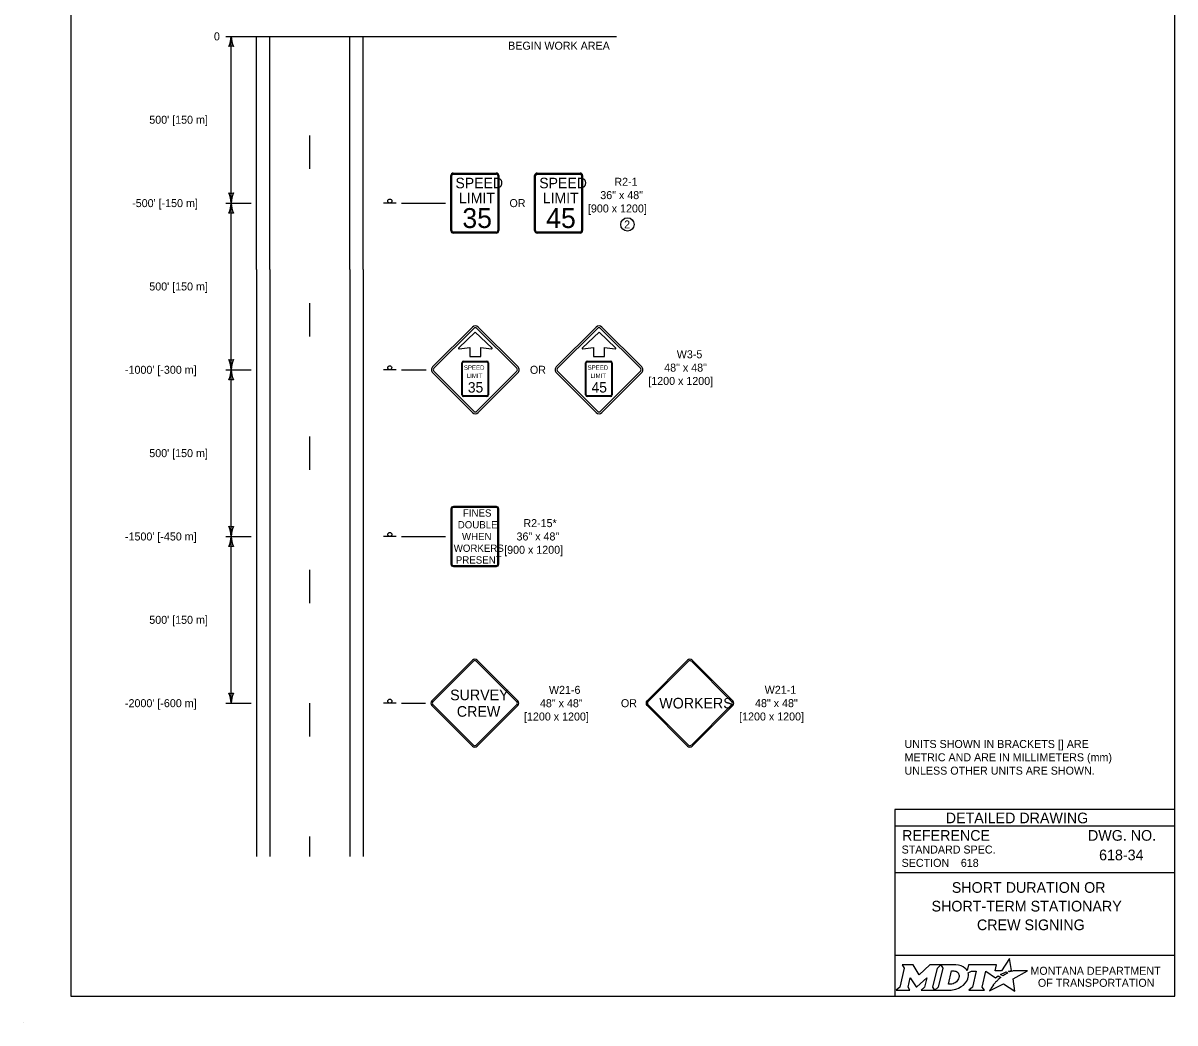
# Model space of a CAD drawing. Extents: x 49991.4 to 50021, y 49987.6 to 50011.4.
# Drawn here: x 49999.98 to 50008.61, y 49999.86 to 50007.36 of the extents above; entities that cross this region are included whole.
import ezdxf

# ---------------------------------------------------------------- set-up
doc = ezdxf.new("R2010")
doc.units = 0
for name, color, linetype in [('Level 1', 7, 'Continuous'), ('Level 2', 7, 'Continuous'), ('Level 3', 7, 'Continuous')]:
    doc.layers.add(name, color=color, linetype=linetype)

msp = doc.modelspace()

# ---------------------------------------------------------------- linework, layer by layer
at = {"layer": 'Level 1'}
for p, q in [((50001.7269, 50005.5137), (50001.7269, 50007.2611)), ((50001.8269, 50005.5137), (50001.8269, 50007.2611)), ((50002.4269, 50005.5137), (50002.4269, 50007.2611)), ((50002.5269, 50005.5137), (50002.5269, 50007.2611)), ((50002.1269, 50006.2688), (50002.1269, 50006.5188)), ((50003.1843, 50005.8044), (50003.1843, 50006.217)), ((50003.1918, 50005.8044), (50003.1918, 50006.217)), ((50003.203, 50006.2357), (50003.5256, 50006.2357)), ((50003.203, 50006.2282), (50003.5256, 50006.2282)), ((50003.5368, 50006.217), (50003.5368, 50005.8044)), ((50003.5443, 50006.217), (50003.5443, 50005.8044)), ((50003.8127, 50005.8045), (50003.8127, 50006.2169)), ((50003.8202, 50005.8045), (50003.8202, 50006.2169)), ((50003.8314, 50006.2357), (50004.154, 50006.2357)), ((50003.8314, 50006.2282), (50004.154, 50006.2282)), ((50004.1652, 50006.2169), (50004.1652, 50005.8045)), ((50004.1727, 50006.2169), (50004.1727, 50005.8045)), ((50002.7749, 50006.0107), (50002.6789, 50006.0107)), ((50003.5256, 50005.7932), (50003.203, 50005.7932)), ((50003.5256, 50005.7857), (50003.203, 50005.7857)), ((50004.154, 50005.7932), (50003.8314, 50005.7932)), ((50004.154, 50005.7857), (50003.8314, 50005.7857)), ((50001.7269, 50005.5137), (50001.7269, 50001.1107)), ((50001.8269, 50005.5137), (50001.8269, 50001.1107)), ((50002.4269, 50005.5137), (50002.4269, 50001.1107)), ((50002.5269, 50005.5137), (50002.5269, 50001.1107)), ((50002.1269, 50005.0111), (50002.1269, 50005.2611)), ((50003.3468, 50005.0813), (50003.0475, 50004.782)), ((50003.3569, 50005.0712), (50003.0576, 50004.7719)), ((50003.3682, 50005.0428), (50003.2438, 50004.9255)), ((50003.3468, 50005.0813), (50003.3468, 50005.0813)), ((50003.3569, 50005.0712), (50003.3569, 50005.0712)), ((50003.4926, 50004.9255), (50003.3682, 50005.0428)), ((50003.6788, 50004.7719), (50003.3795, 50005.0712)), ((50003.6889, 50004.782), (50003.3896, 50005.0813)), ((50004.2743, 50005.0813), (50003.9749, 50004.782)), ((50004.2843, 50005.0712), (50003.985, 50004.7719)), ((50004.2956, 50005.0428), (50004.1712, 50004.9255)), ((50004.2743, 50005.0813), (50004.2743, 50005.0813)), ((50004.2843, 50005.0712), (50004.2843, 50005.0712)), ((50004.4201, 50004.9255), (50004.2956, 50005.0428)), ((50004.6062, 50004.7719), (50004.3069, 50005.0712)), ((50004.6163, 50004.782), (50004.317, 50005.0813)), ((50003.2478, 50004.9169), (50003.3279, 50004.9269)), ((50003.3279, 50004.9269), (50003.3279, 50004.8614)), ((50003.4085, 50004.8614), (50003.4085, 50004.9269)), ((50003.4085, 50004.9269), (50003.4885, 50004.9169)), ((50004.1753, 50004.9169), (50004.2553, 50004.9269)), ((50004.2553, 50004.9269), (50004.2553, 50004.8614)), ((50004.336, 50004.8614), (50004.336, 50004.9269)), ((50004.336, 50004.9269), (50004.416, 50004.9169)), ((50003.2678, 50004.5725), (50003.2678, 50004.8138)), ((50003.273, 50004.5725), (50003.273, 50004.8138)), ((50003.2803, 50004.8263), (50003.455, 50004.8263)), ((50003.2803, 50004.8211), (50003.455, 50004.8211)), ((50003.3279, 50004.8614), (50003.4085, 50004.8614)), ((50003.3677, 50004.8263), (50003.3677, 50004.8263)), ((50003.4623, 50004.8138), (50003.4623, 50004.5725)), ((50003.4675, 50004.8138), (50003.4675, 50004.5725)), ((50004.1953, 50004.5725), (50004.1953, 50004.8138)), ((50004.2005, 50004.5725), (50004.2005, 50004.8138)), ((50004.2078, 50004.8263), (50004.3825, 50004.8263)), ((50004.2078, 50004.8211), (50004.3825, 50004.8211)), ((50004.2553, 50004.8614), (50004.336, 50004.8614)), ((50004.2951, 50004.8263), (50004.2951, 50004.8263)), ((50004.3898, 50004.8138), (50004.3898, 50004.5725)), ((50004.395, 50004.8138), (50004.395, 50004.5725)), ((50002.7749, 50004.7607), (50002.6789, 50004.7607)), ((50003.0475, 50004.7392), (50003.3468, 50004.4399)), ((50003.0576, 50004.7493), (50003.3569, 50004.45)), ((50003.3795, 50004.45), (50003.6788, 50004.7493)), ((50003.3896, 50004.4399), (50003.6889, 50004.7392)), ((50003.9749, 50004.7392), (50004.2743, 50004.4399)), ((50003.985, 50004.7493), (50004.2843, 50004.45)), ((50004.3069, 50004.45), (50004.6062, 50004.7493)), ((50004.317, 50004.4399), (50004.6163, 50004.7392)), ((50003.455, 50004.5652), (50003.2803, 50004.5652)), ((50003.455, 50004.56), (50003.2803, 50004.56)), ((50004.3825, 50004.5652), (50004.2078, 50004.5652)), ((50004.3825, 50004.56), (50004.2078, 50004.56)), ((50002.1269, 50004.0111), (50002.1269, 50004.2611)), ((50003.1846, 50003.7169), (50003.1846, 50003.3043)), ((50003.1922, 50003.7169), (50003.1922, 50003.3043)), ((50003.5258, 50003.7355), (50003.2034, 50003.7355)), ((50003.5258, 50003.7281), (50003.2034, 50003.7281)), ((50003.5372, 50003.3043), (50003.5372, 50003.7169)), ((50003.5446, 50003.3043), (50003.5446, 50003.7169)), ((50002.7749, 50003.5107), (50002.6789, 50003.5107)), ((50002.1269, 50003.0111), (50002.1269, 50003.2611)), ((50003.2034, 50003.2931), (50003.5258, 50003.2931)), ((50003.2034, 50003.2855), (50003.5258, 50003.2855)), ((50003.3466, 50002.5821), (50003.0425, 50002.2781)), ((50003.3537, 50002.5751), (50003.0496, 50002.2711)), ((50003.6789, 50002.2711), (50003.3749, 50002.5751)), ((50003.686, 50002.2781), (50003.3819, 50002.5821)), ((50004.9598, 50002.5822), (50004.6557, 50002.2782)), ((50004.9669, 50002.5752), (50004.6628, 50002.271)), ((50005.2921, 50002.271), (50004.9881, 50002.5752)), ((50005.2992, 50002.2782), (50004.9951, 50002.5822)), ((50002.1269, 50002.0111), (50002.1269, 50002.2611)), ((50002.7749, 50002.2605), (50002.6789, 50002.2605)), ((50003.0425, 50002.2427), (50003.3466, 50001.9387)), ((50003.0496, 50002.2499), (50003.3537, 50001.9457)), ((50003.3749, 50001.9457), (50003.6789, 50002.2499)), ((50003.3819, 50001.9387), (50003.686, 50002.2427)), ((50004.6557, 50002.2428), (50004.9598, 50001.9388)), ((50004.6628, 50002.2498), (50004.9669, 50001.9458)), ((50004.9881, 50001.9458), (50005.2921, 50002.2498)), ((50004.9951, 50001.9388), (50005.2992, 50002.2428)), ((50002.1269, 50001.1107), (50002.1269, 50001.2611)), ((49999.9766, 49999.8624), (49999.9766, 49999.8624))]:
    msp.add_line(p, q, dxfattribs=at)
msp.add_lwpolyline([(50008.6146, 50011.2628), (50000.3356, 50011.2628), (50000.3356, 50000.0624), (50008.6146, 50000.0624)], close=True, dxfattribs=at)
for centre in [(50002.7269, 50006.0259), (50002.7268, 50004.7758), (50002.7269, 50003.5258), (50002.7269, 50002.2756)]:
    msp.add_circle(centre, 0.0152, dxfattribs=at)
for centre, radius, start, end in [((50003.2031, 50006.217), 0.0187, 90, 180), ((50003.2031, 50006.217), 0.0113, 90, 180), ((50003.5256, 50006.217), 0.0187, 0, 90), ((50003.5256, 50006.217), 0.0113, 0, 90), ((50003.8315, 50006.217), 0.0187, 90, 180), ((50003.8315, 50006.217), 0.0113, 90, 180), ((50004.154, 50006.217), 0.0187, 0, 90), ((50004.154, 50006.217), 0.0113, 0, 90), ((50003.2031, 50005.8045), 0.0187, 180, 270), ((50003.2031, 50005.8045), 0.0113, 180, 270), ((50003.5256, 50005.8045), 0.0187, 270, 0), ((50003.5256, 50005.8045), 0.0113, 270, 0), ((50003.8315, 50005.8045), 0.0187, 180, 270), ((50003.8315, 50005.8045), 0.0113, 180, 270), ((50004.154, 50005.8045), 0.0187, 270, 0), ((50004.154, 50005.8045), 0.0113, 270, 0), ((50003.3682, 50005.0599), 0.0302, 45.00007, 134.99993), ((50003.3682, 50005.0599), 0.016, 45.00007, 134.99993), ((50004.2956, 50005.0599), 0.0302, 45.00007, 134.99993), ((50004.2956, 50005.0599), 0.016, 45.00007, 134.99993), ((50003.2473, 50004.9219), 0.00508, 134.62874, 275.82948), ((50003.489, 50004.9219), 0.00509, 264.38259, 45.16491), ((50004.1748, 50004.9219), 0.00508, 134.62874, 275.82948), ((50004.4165, 50004.9219), 0.00509, 264.38259, 45.16491), ((50003.0689, 50004.7606), 0.0302, 134.99993, 225.00008), ((50003.2803, 50004.8138), 0.0125, 90, 180), ((50003.2803, 50004.8138), 0.00728, 90, 180), ((50003.455, 50004.8138), 0.0125, 360, 90), ((50003.455, 50004.8138), 0.00728, 360, 90), ((50003.6675, 50004.7606), 0.0302, 314.99993, 45.00008), ((50003.9963, 50004.7606), 0.0302, 134.99993, 225.00008), ((50004.2078, 50004.8138), 0.0125, 90, 180), ((50004.2078, 50004.8138), 0.00728, 90, 180), ((50004.3825, 50004.8138), 0.0125, 360, 90), ((50004.3825, 50004.8138), 0.00728, 360, 90), ((50004.5949, 50004.7606), 0.0302, 314.99993, 45.00008), ((50003.0689, 50004.7606), 0.016, 134.99993, 225.00008), ((50003.6675, 50004.7606), 0.016, 314.99993, 45.00007), ((50003.9963, 50004.7606), 0.016, 134.99993, 225.00008), ((50004.5949, 50004.7606), 0.016, 314.99993, 45.00007), ((50003.2803, 50004.5725), 0.0125, 180, 270), ((50003.2803, 50004.5725), 0.00728, 180, 270), ((50003.455, 50004.5725), 0.00728, 270, 360), ((50003.455, 50004.5725), 0.0125, 270, 360), ((50004.2078, 50004.5725), 0.0125, 180, 270), ((50004.2078, 50004.5725), 0.00728, 180, 270), ((50004.3825, 50004.5725), 0.00728, 270, 360), ((50004.3825, 50004.5725), 0.0125, 270, 360), ((50003.3682, 50004.4613), 0.0302, 225.00007, 314.99993), ((50003.3682, 50004.4613), 0.016, 225.00007, 314.99993), ((50004.2956, 50004.4613), 0.0302, 225.00007, 314.99993), ((50004.2956, 50004.4613), 0.016, 225.00007, 314.99993), ((50003.2034, 50003.7168), 0.0187, 90, 180), ((50003.2034, 50003.7168), 0.0113, 90, 180), ((50003.5259, 50003.7168), 0.0187, 360, 90), ((50003.5259, 50003.7168), 0.0113, 360, 90), ((50003.2034, 50003.3043), 0.0187, 180, 270), ((50003.2034, 50003.3043), 0.0113, 180, 270), ((50003.5259, 50003.3043), 0.0187, 270, 360), ((50003.5259, 50003.3043), 0.0113, 270, 360), ((50003.3642, 50002.5645), 0.025, 45, 135), ((50003.3642, 50002.5645), 0.015, 45, 135), ((50004.9773, 50002.5645), 0.025, 45, 135), ((50004.9773, 50002.5645), 0.015, 45, 135), ((50003.0602, 50002.2604), 0.025, 135, 225), ((50003.6683, 50002.2604), 0.025, 315, 45.00024), ((50004.6732, 50002.2604), 0.025, 135, 225), ((50005.2814, 50002.2604), 0.025, 315, 45.00024), ((50003.0602, 50002.2604), 0.015, 135, 225), ((50003.6683, 50002.2604), 0.015, 315, 45.00024), ((50004.6732, 50002.2604), 0.015, 135, 225), ((50005.2814, 50002.2604), 0.015, 315, 45.00024), ((50003.3642, 50001.9563), 0.025, 225, 314.99957), ((50003.3642, 50001.9563), 0.015, 225, 314.99957), ((50004.9773, 50001.9563), 0.025, 225, 314.99957), ((50004.9773, 50001.9563), 0.015, 225, 314.99957)]:
    msp.add_arc(centre, radius, start, end, dxfattribs=at)
at = {"layer": 'Level 2'}
for p, q in [((50008.6146, 50001.4624), (50006.5146, 50001.4624)), ((50006.5146, 50001.4624), (50006.5146, 50000.0624)), ((50008.6146, 50001.3374), (50006.5146, 50001.3374)), ((50008.2507, 50001.1223), (50008.2507, 50001.1223)), ((50008.6146, 50000.9874), (50006.5146, 50000.9874)), ((50007.0089, 50001.0629), (50007.0089, 50001.0629)), ((50007.5646, 50000.7383), (50007.5646, 50000.7383)), ((50008.6146, 50000.3693), (50006.5146, 50000.3693))]:
    msp.add_line(p, q, dxfattribs=at)
for points in [[(50006.5701, 50000.2974), (50006.5842, 50000.274), (50006.5507, 50000.1307), (50006.525, 50000.1082), (50006.6266, 50000.1082), (50006.6131, 50000.131), (50006.6293, 50000.2011), (50006.673, 50000.1321), (50006.6783, 50000.1321), (50006.7534, 50000.2016), (50006.737, 50000.1305), (50006.7123, 50000.1085), (50006.8139, 50000.1085), (50006.8001, 50000.1318), (50006.8333, 50000.2742)], [(50006.8333, 50000.2742), (50006.8586, 50000.2974), (50006.7762, 50000.2974), (50006.6966, 50000.2244), (50006.6521, 50000.2971), (50006.5701, 50000.2974)], [(50006.9722, 50000.2974), (50006.8586, 50000.2974), (50006.8733, 50000.2745), (50006.8394, 50000.1307), (50006.8139, 50000.1085), (50006.9245, 50000.1085)], [(50007.3771, 50000.2447), (50007.3668, 50000.2503), (50007.3784, 50000.2531), (50007.39, 50000.2551), (50007.3726, 50000.3452), (50007.3131, 50000.2539), (50007.2658, 50000.2532), (50007.2761, 50000.2973), (50007.0669, 50000.2974), (50007.0568, 50000.2549), (50007.051, 50000.2632)], [(50006.9962, 50000.2107), (50006.995, 50000.2026), (50006.9918, 50000.1933), (50006.9876, 50000.1851), (50006.982, 50000.1776), (50006.9755, 50000.1707), (50006.9676, 50000.1644), (50006.9593, 50000.1597), (50006.9502, 50000.1558), (50006.9411, 50000.1535), (50006.9319, 50000.1526), (50006.916, 50000.1526), (50006.9396, 50000.2526), (50006.9556, 50000.2526), (50006.9632, 50000.252), (50006.9708, 50000.2501), (50006.9774, 50000.2471), (50006.9835, 50000.2429), (50006.9883, 50000.2379), (50006.992, 50000.2319), (50006.9947, 50000.2257), (50006.9963, 50000.2183), (50006.9963, 50000.2153), (50006.9962, 50000.2107)], [(50007.0636, 50000.2383), (50007.0882, 50000.2514), (50007.1251, 50000.2514), (50007.0965, 50000.1309), (50007.069, 50000.1082), (50007.1852, 50000.1082), (50007.1682, 50000.1311), (50007.1964, 50000.2513), (50007.2677, 50000.1996), (50007.2888, 50000.2147), (50007.3085, 50000.2038)], [(50007.2527, 50000.1479), (50007.2374, 50000.1235), (50007.2327, 50000.116), (50007.2269, 50000.1074), (50007.2246, 50000.1031), (50007.3299, 50000.1562), (50007.4138, 50000.1011), (50007.4007, 50000.1938), (50007.5076, 50000.2522), (50007.4583, 50000.253), (50007.4282, 50000.2534), (50007.4074, 50000.2537), (50007.4006, 50000.2522), (50007.3957, 50000.251), (50007.3873, 50000.2487), (50007.3771, 50000.2447)], [(50007.3267, 50000.2171), (50007.3243, 50000.2154), (50007.306, 50000.225), (50007.3163, 50000.2307), (50007.3204, 50000.2329), (50007.329, 50000.2369), (50007.3347, 50000.2395), (50007.3426, 50000.2425), (50007.3499, 50000.2452), (50007.3617, 50000.2378), (50007.3577, 50000.2357), (50007.3531, 50000.2332), (50007.3489, 50000.231), (50007.3439, 50000.2281), (50007.342, 50000.227), (50007.3393, 50000.2254), (50007.3368, 50000.224), (50007.3345, 50000.2224), (50007.3319, 50000.2206), (50007.3292, 50000.2188), (50007.3267, 50000.2171)], [(50006.9702, 50000.1158), (50006.9786, 50000.1184), (50006.9916, 50000.1238), (50007.012, 50000.1348)], [(50007.2666, 50000.164), (50007.2666, 50000.164)]]:
    msp.add_lwpolyline(points, dxfattribs=at)
msp.add_circle((50004.5091, 50005.8506), 0.05, dxfattribs=at)
for centre, radius, start, end in [((50006.9953, 50000.219), 0.0709, 339.53292, 15.85821), ((50006.9513, 50000.2363), 0.1183, 300.91025, 339.13831)]:
    msp.add_arc(centre, radius, start, end, dxfattribs=at)
for centre, major_axis, ratio, start_param, end_param in [((50006.9701, 50000.25), (0.0834, -0.0037), 0.568097, 0.61298, 1.570796), ((50007.0257, 50000.2573), (0.0361, -0.0295), 0.469099, 1.225588, 1.570796), ((50007.2974, 50000.1941), (-0.0112, -0.0097), 0.021651, 3.157348, 6.283185), ((50006.9248, 50000.2568), (0, 0.1484), 0.987302, 3.139398, 3.456847), ((50007.2597, 50000.1559), (-0.00694, -0.00806), 0.008222, 0, 3.137361), ((50007.2764, 50000.1742), (-0.0098, -0.0102), 0.016458, 3.141593, 6.279097)]:
    msp.add_ellipse(centre, major_axis=major_axis, ratio=ratio, start_param=start_param, end_param=end_param, dxfattribs=at)
at = {"layer": 'Level 3'}
for p, q in [((50001.4969, 50007.2611), (50004.4271, 50007.2611)), ((50001.5369, 50006.6359), (50001.5369, 50007.2611)), ((50001.5369, 50006.0107), (50001.5369, 50006.6359)), ((50001.4969, 50006.0107), (50001.6869, 50006.0107)), ((50001.5369, 50004.7607), (50001.5369, 50006.0105)), ((50002.8149, 50006.0107), (50003.1443, 50006.0107)), ((50001.4969, 50004.7607), (50001.6869, 50004.7607)), ((50001.5369, 50003.5107), (50001.5369, 50004.7607)), ((50002.8149, 50004.7607), (50002.9986, 50004.7607)), ((50001.4969, 50003.5107), (50001.6869, 50003.5107)), ((50001.5369, 50002.2605), (50001.5369, 50003.5107)), ((50002.8149, 50003.5107), (50003.1446, 50003.5107)), ((50001.4969, 50002.2605), (50001.6869, 50002.2605)), ((50002.8149, 50002.2605), (50002.9952, 50002.2605))]:
    msp.add_line(p, q, dxfattribs=at)
for centre, radius, start, end in [((50001.3148, 50007.2703), 0.2223, 337.45601, 357.63952), ((50001.7696, 50007.2726), 0.233, 182.82731, 202.07716), ((50001.5369, 50007.1329), 0.0548, 72.13882, 107.86118), ((50001.5369, 50006.1389), 0.0548, 252.13882, 287.86118), ((50001.3042, 50005.9992), 0.233, 2.82731, 22.07716), ((50001.759, 50006.0015), 0.2223, 157.45601, 177.63952), ((50001.3148, 50006.0196), 0.2223, 337.45601, 357.63952), ((50001.7696, 50006.022), 0.233, 182.82731, 202.07716), ((50001.5369, 50005.8823), 0.0548, 72.13882, 107.86118), ((50001.5369, 50004.8889), 0.0548, 252.13882, 287.86118), ((50001.3042, 50004.7492), 0.233, 2.82731, 22.07716), ((50001.759, 50004.7515), 0.2223, 157.45601, 177.63952), ((50001.3148, 50004.7698), 0.2223, 337.45601, 357.63952), ((50001.7696, 50004.7722), 0.233, 182.82731, 202.07716), ((50001.5369, 50004.6325), 0.0548, 72.13882, 107.86118), ((50001.5369, 50003.6389), 0.0548, 252.13882, 287.86118), ((50001.3042, 50003.4992), 0.233, 2.82731, 22.07716), ((50001.759, 50003.5015), 0.2223, 157.45601, 177.63952), ((50001.3148, 50003.5198), 0.2223, 337.45601, 357.63952), ((50001.7696, 50003.5222), 0.233, 182.82731, 202.07716), ((50001.5369, 50003.3825), 0.0548, 72.13882, 107.86118), ((50001.5369, 50002.3887), 0.0548, 252.13882, 287.86118), ((50001.3042, 50002.249), 0.233, 2.82731, 22.07716), ((50001.759, 50002.2513), 0.2223, 157.45601, 177.63952)]:
    msp.add_arc(centre, radius, start, end, dxfattribs=at)

# ---------------------------------------------------------------- texts
at = {"layer": 'Level 1'}
for s, height, p in [('SPEED', 0.07884, (50003.2191, 50006.122)), ('SPEED', 0.07884, (50003.8475, 50006.122)), ('LIMIT', 0.07884, (50003.2456, 50006.0095)), ('LIMIT', 0.07884, (50003.874, 50006.0094)), ('35', 0.14918, (50003.2711, 50005.824)), ('45', 0.14918, (50003.8995, 50005.824)), ('SURVEY', 0.07975, (50003.1794, 50002.2826)), ('WORKERS', 0.0797, (50004.7477, 50002.2208)), ('CREW', 0.07975, (50003.2294, 50002.1588))]:
    msp.add_text(s, height=height, dxfattribs=at).set_placement(p)
for s, height, p in [('SPEED', 0.03301, (50003.2823, 50004.7606)), ('SPEED', 0.03301, (50004.2098, 50004.7606)), ('LIMIT', 0.03301, (50003.3042, 50004.6996)), ('LIMIT', 0.03301, (50004.2316, 50004.6996)), ('35', 0.07775, (50003.3122, 50004.5902)), ('45', 0.07775, (50004.2396, 50004.5902)), ('FINES', 0.05437, (50003.2748, 50003.6597)), ('DOUBLE', 0.05437, (50003.2362, 50003.5717)), ('WHEN', 0.05437, (50003.2677, 50003.4836)), ('WORKERS', 0.05437, (50003.206, 50003.3955)), ('PRESENT', 0.05437, (50003.2221, 50003.3074))]:
    msp.add_text(s, height=height, rotation=360, dxfattribs=at).set_placement(p)
at = {"layer": 'Level 2'}
for s, height, p in [('0', 0.06, (50001.4081, 50007.2311)), ('BEGIN WORK AREA', 0.06, (50003.6144, 50007.1611)), ("500' [150 m]", 0.06, (50000.9235, 50006.6059)), ('R2-1', 0.06, (50004.4108, 50006.1406)), ('36" x 48"', 0.06, (50004.3052, 50006.0406)), ("-500' [-150 m]", 0.06, (50000.795, 50005.9807)), ('OR', 0.06, (50003.6243, 50005.9807)), ('[900 x 1200]', 0.06, (50004.2127, 50005.9406)), ('2', 0.06, (50004.4839, 50005.8206)), ("500' [150 m]", 0.06, (50000.9235, 50005.3556)), ('W3-5', 0.06, (50004.8787, 50004.8471)), ("-1000' [-300 m]", 0.06, (50000.7411, 50004.7307)), ('OR', 0.06, (50003.7777, 50004.7306)), ('48" x 48"', 0.06, (50004.7846, 50004.7471)), ('[1200 x 1200]', 0.06, (50004.6652, 50004.6471)), ("500' [150 m]", 0.06, (50000.9235, 50004.1057)), ('R2-15*', 0.06, (50003.7287, 50003.5809)), ("-1500' [-450 m]", 0.06, (50000.7411, 50003.4807)), ('36" x 48"', 0.06, (50003.6771, 50003.4809)), ('[900 x 1200]', 0.06, (50003.5846, 50003.3809)), ("500' [150 m]", 0.06, (50000.9235, 50002.8556)), ('W21-6', 0.06, (50003.9202, 50002.3304)), ('W21-1', 0.06, (50005.5381, 50002.3307)), ("-2000' [-600 m]", 0.06, (50000.7411, 50002.2305)), ('48" x 48"', 0.06, (50003.8527, 50002.2304)), ('OR', 0.06, (50004.4599, 50002.2304)), ('48" x 48"', 0.06, (50005.4658, 50002.2307)), ('[1200 x 1200]', 0.06, (50003.7333, 50002.1304)), ('[1200 x 1200]', 0.06, (50005.3464, 50002.1307)), ('UNITS SHOWN IN BRACKETS [] ARE ', 0.06, (50006.5865, 50001.9247)), ('METRIC AND ARE IN MILLIMETERS (mm) ', 0.06, (50006.5865, 50001.8247)), ('UNLESS OTHER UNITS ARE SHOWN.', 0.06, (50006.5865, 50001.7247)), ('DETAILED DRAWING', 0.0799, (50006.8956, 50001.3599)), ('REFERENCE', 0.08, (50006.5682, 50001.229)), ('DWG. NO.', 0.08, (50007.9624, 50001.229)), ('STANDARD SPEC.', 0.06, (50006.5649, 50001.133)), ('618-34', 0.08, (50008.0456, 50001.0823)), ('SECTION', 0.06, (50006.5649, 50001.033)), ('618', 0.06, (50007.0089, 50001.0329)), ('SHORT DURATION OR', 0.08, (50006.941, 50000.8383)), ('SHORT-TERM STATIONARY', 0.08, (50006.7894, 50000.6983)), ('CREW SIGNING', 0.08, (50007.1299, 50000.5583)), ('MONTANA DEPARTMENT', 0.06, (50007.5308, 50000.2236)), ('OF TRANSPORTATION', 0.06, (50007.587, 50000.1336))]:
    msp.add_text(s, height=height, dxfattribs=at).set_placement(p)

doc.saveas('drawing.dxf')
